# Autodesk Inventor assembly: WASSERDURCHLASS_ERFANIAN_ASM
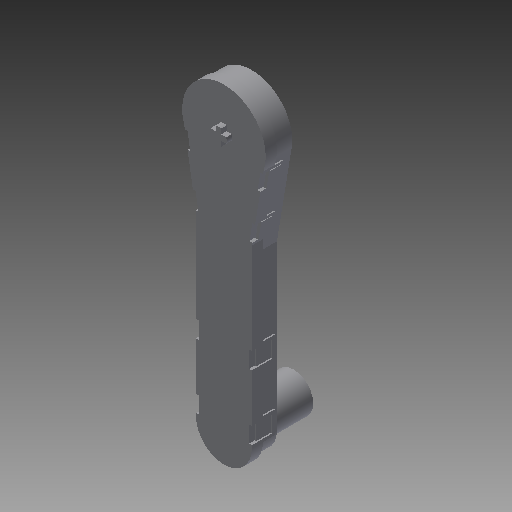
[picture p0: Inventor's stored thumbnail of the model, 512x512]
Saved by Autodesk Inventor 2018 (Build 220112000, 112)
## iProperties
Created: 2019-01
Part Number: WASSERDURCHLASS_ERFANIAN_ASM
Material: Generisch
Document SubType Name: Assembly
Designer: zand
Author: zand
Revision Number: 7LAST_VERSION
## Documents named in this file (3)
- W:\KAFFEEMASCHINE\Creo5-STEP-Inventor\STEP\WASSERDURCHLASS_ERFANIAN_ASM.iam
- W:\KAFFEEMASCHINE\Creo5-STEP-Inventor\STEP\WASSERDURCHLASS_ERFANIAN.ipt
- W:\KAFFEEMASCHINE\Creo5-STEP-Inventor\STEP\WASSERDURCHLAS_UNTER_ERFANIAN.ipt
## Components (2 placed, 2 different names)
1. Wasserdurchlass
2. Wasserdurchlass_unten
